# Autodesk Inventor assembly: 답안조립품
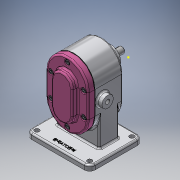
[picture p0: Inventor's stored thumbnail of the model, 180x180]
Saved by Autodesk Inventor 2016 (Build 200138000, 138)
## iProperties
Created: 2020-09
Part Number: 답안조립품
Material: 일반
Document SubType Name: Assembly
Designer: Windows7
Author: Windows7
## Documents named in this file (11)
- C:\Users\Windows7\Desktop\700906V1045\답안조립품.iam
- C:\Users\Windows7\Desktop\700906V1045\본체.ipt
- C:\Users\Windows7\Desktop\700906V1045\개스킷.ipt
- C:\Users\Windows7\Desktop\700906V1045\메인축.ipt
- C:\Users\Windows7\Desktop\700906V1045\베어링부시.ipt
- C:\Users\Windows7\Desktop\700906V1045\볼트 M5.ipt
- C:\Users\Windows7\Desktop\700906V1045\서브축.ipt
- C:\Users\Windows7\Desktop\700906V1045\스퍼기어.ipt
- C:\Users\Windows7\Desktop\700906V1045\오일 실 16 28 7.ipt
- C:\Users\Windows7\Desktop\700906V1045\커버.ipt
- C:\Users\Windows7\Desktop\700906V1045\키 6 x 6 x 18.ipt
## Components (1 placed, 1 different names)
1. 개스킷:1
## Component patterns: 구성요소 패턴 1:2 (2 elements)
